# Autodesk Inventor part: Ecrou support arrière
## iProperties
Shininess: 20.0
Angle Display Precision: 2
Document Length Units: 11269
Document Angle Units: 11279
Document Time Units: 11290
Document Mass Units: 11283
Document Length Units Precision: 3
Document Angle Units Precision: 2
Created: 2002-09
Part Number: Ecrou support arrière
Material: Par défaut
Document SubType Name: Modélisation
Designer: administrateur
Density: 0.0
Volumn: 0.0
Area: 0.0
PropertySet Name: Model Information
Control State: 0
Master: False
Checked Out: False
Author: administrateur
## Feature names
1. Extrusion1
